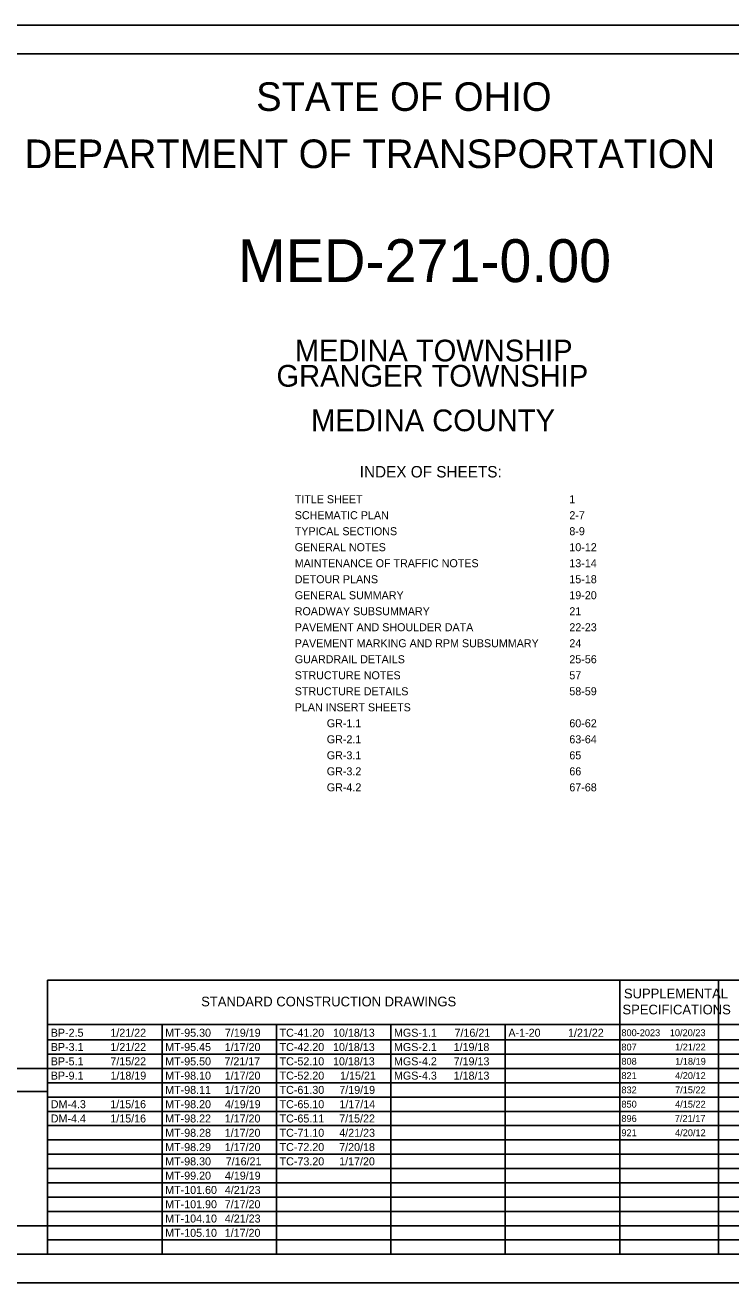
# Model space of a CAD drawing. Extents: x 0 to 34, y 0 to 22.
# Drawn here: x 9.76 to 22.09, y 0 to 22 of the extents above; entities that cross this region are included whole.
import ezdxf

# ---------------------------------------------------------------- set-up
doc = ezdxf.new("R2010")
doc.units = 0
for name, color, linetype in [('SH_Border', 7, 'Continuous'), ('SH_Cut_Line', 7, 'Continuous'), ('SH_Data', 7, 'Continuous'), ('SH_Text', 7, 'Continuous')]:
    doc.layers.add(name, color=color, linetype=linetype)

msp = doc.modelspace()

# ---------------------------------------------------------------- linework, layer by layer
at = {"layer": 'SH_Border'}
msp.add_lwpolyline([(1.5, 21.5), (33.5, 21.5), (33.5, 0.5), (1.5, 0.5)], close=True, dxfattribs=at)
at = {"layer": 'SH_Cut_Line'}
msp.add_lwpolyline([(0, 0), (34, 0), (34, 22), (0, 22)], close=True, dxfattribs=at)
at = {"layer": 'SH_Data'}
for p, q in [((10.15, 5.292), (23.6, 5.292)), ((10.15, 0.5), (10.15, 5.292)), ((20.15, 0.5), (20.15, 5.292)), ((21.875, 0.5), (21.875, 5.292)), ((10.15, 4.521), (23.6, 4.521)), ((12.15, 0.5), (12.15, 4.521)), ((14.15, 0.5), (14.15, 4.521)), ((16.15, 0.5), (16.15, 4.521)), ((18.15, 0.5), (18.15, 4.521)), ((10.15, 4.25), (23.6, 4.25)), ((10.15, 4), (23.6, 4)), ((10.15, 3.75), (7.35, 3.75)), ((10.15, 3.75), (23.6, 3.75)), ((10.15, 0.5), (10.15, 3.75)), ((10.15, 3.35), (7.35, 3.35)), ((10.15, 3.5), (23.6, 3.5)), ((10.15, 3.25), (23.6, 3.25)), ((10.15, 3), (23.6, 3)), ((10.15, 2.75), (23.6, 2.75)), ((10.15, 2.5), (23.6, 2.5)), ((10.15, 2.25), (23.6, 2.25)), ((10.15, 2), (23.6, 2)), ((10.15, 1.75), (23.6, 1.75)), ((10.15, 1.5), (23.6, 1.5)), ((10.15, 1.25), (23.6, 1.25)), ((10.15, 1), (23.6, 1)), ((10.15, 0.75), (23.6, 0.75)), ((10.15, 0.5), (7.35, 0.5))]:
    msp.add_line(p, q, dxfattribs=at)
msp.add_lwpolyline([(10.15, 0.5), (10.15, 1), (7.35, 1), (7.35, 0.5)], close=True, dxfattribs=at)

# ---------------------------------------------------------------- texts
at = {"layer": 'SH_Text'}
for s, height, p in [('STATE OF OHIO', 0.5, (13.795, 20.5)), ('DEPARTMENT OF TRANSPORTATION', 0.5, (9.747, 19.5)), ('MED-271-0.00', 0.75, (13.478, 17.505)), ('MEDINA TOWNSHIP', 0.38, (14.471, 16.118)), ('GRANGER TOWNSHIP', 0.38, (14.151, 15.676)), ('MEDINA COUNTY', 0.38, (14.756, 14.897)), ('INDEX OF SHEETS:', 0.2, (15.606, 14.088)), ('TITLE SHEET', 0.14, (14.47, 13.638)), ('1', 0.14, (19.27, 13.638)), ('SCHEMATIC PLAN', 0.14, (14.47, 13.358)), ('2-7', 0.14, (19.27, 13.358)), ('TYPICAL SECTIONS', 0.14, (14.47, 13.078)), ('8-9', 0.14, (19.27, 13.078)), ('GENERAL NOTES', 0.14, (14.47, 12.798)), ('10-12', 0.14, (19.27, 12.798)), ('MAINTENANCE OF TRAFFIC NOTES', 0.14, (14.47, 12.518)), ('13-14', 0.14, (19.27, 12.518)), ('DETOUR PLANS', 0.14, (14.47, 12.238)), ('15-18', 0.14, (19.27, 12.238)), ('GENERAL SUMMARY', 0.14, (14.47, 11.958)), ('19-20', 0.14, (19.27, 11.958)), ('ROADWAY SUBSUMMARY', 0.14, (14.47, 11.678)), ('21', 0.14, (19.27, 11.678)), ('PAVEMENT AND SHOULDER DATA', 0.14, (14.47, 11.398)), ('22-23', 0.14, (19.27, 11.398)), ('PAVEMENT MARKING AND RPM SUBSUMMARY', 0.14, (14.47, 11.118)), ('24', 0.14, (19.27, 11.118)), ('GUARDRAIL DETAILS', 0.14, (14.47, 10.838)), ('25-56', 0.14, (19.27, 10.838)), ('STRUCTURE NOTES', 0.14, (14.47, 10.558)), ('57', 0.14, (19.27, 10.558)), ('STRUCTURE DETAILS', 0.14, (14.47, 10.278)), ('58-59', 0.14, (19.27, 10.278)), ('PLAN INSERT SHEETS', 0.14, (14.47, 9.998)), ('GR-1.1', 0.14, (15.03, 9.718)), ('60-62', 0.14, (19.27, 9.718)), ('GR-2.1', 0.14, (15.03, 9.438)), ('63-64', 0.14, (19.27, 9.438)), ('GR-3.1', 0.14, (15.03, 9.158)), ('65', 0.14, (19.27, 9.158)), ('GR-3.2', 0.14, (15.03, 8.878)), ('66', 0.14, (19.27, 8.878)), ('GR-4.2', 0.14, (15.03, 8.598)), ('67-68', 0.14, (19.27, 8.598)), ('SUPPLEMENTAL', 0.17, (20.224, 4.976)), ('STANDARD CONSTRUCTION DRAWINGS', 0.17, (12.834, 4.836)), ('SPECIFICATIONS', 0.17, (20.198, 4.696)), ('BP-2.5', 0.14, (10.205, 4.305)), ('1/21/22', 0.14, (11.247, 4.305)), ('MT-95.30', 0.14, (12.205, 4.305)), ('7/19/19', 0.14, (13.249, 4.305)), ('TC-41.20', 0.14, (14.205, 4.305)), ('10/18/13', 0.14, (15.139, 4.305)), ('MGS-1.1', 0.14, (16.205, 4.305)), ('7/16/21', 0.14, (17.263, 4.305)), ('A-1-20', 0.14, (18.205, 4.305)), ('1/21/22', 0.14, (19.247, 4.305)), ('800-2023', 0.12, (20.18, 4.315)), ('10/20/23', 0.12, (21.026, 4.315)), ('BP-3.1', 0.14, (10.205, 4.055)), ('1/21/22', 0.14, (11.247, 4.055)), ('MT-95.45', 0.14, (12.205, 4.055)), ('1/17/20', 0.14, (13.246, 4.055)), ('TC-42.20', 0.14, (14.205, 4.055)), ('10/18/13', 0.14, (15.139, 4.055)), ('MGS-2.1', 0.14, (16.205, 4.055)), ('1/19/18', 0.14, (17.247, 4.055)), ('807', 0.12, (20.18, 4.065)), ('1/21/22', 0.12, (21.118, 4.065)), ('BP-5.1', 0.14, (10.205, 3.805)), ('7/15/22', 0.14, (11.247, 3.805)), ('MT-95.50', 0.14, (12.205, 3.805)), ('7/21/17', 0.14, (13.241, 3.805)), ('TC-52.10', 0.14, (14.205, 3.805)), ('10/18/13', 0.14, (15.139, 3.805)), ('MGS-4.2', 0.14, (16.205, 3.805)), ('7/19/13', 0.14, (17.248, 3.805)), ('808', 0.12, (20.18, 3.815)), ('1/18/19', 0.12, (21.12, 3.815)), ('BP-9.1', 0.14, (10.205, 3.555)), ('1/18/19', 0.14, (11.249, 3.555)), ('MT-98.10', 0.14, (12.205, 3.555)), ('1/17/20', 0.14, (13.246, 3.555)), ('TC-52.20', 0.14, (14.205, 3.555)), ('1/15/21', 0.14, (15.263, 3.555)), ('MGS-4.3', 0.14, (16.205, 3.555)), ('1/18/13', 0.14, (17.248, 3.555)), ('821', 0.12, (20.18, 3.565)), ('4/20/12', 0.12, (21.118, 3.565)), ('MT-98.11', 0.14, (12.205, 3.305)), ('1/17/20', 0.14, (13.246, 3.305)), ('TC-61.30', 0.14, (14.205, 3.305)), ('7/19/19', 0.14, (15.249, 3.305)), ('832', 0.12, (20.18, 3.315)), ('7/15/22', 0.12, (21.118, 3.315)), ('DM-4.3', 0.14, (10.205, 3.055)), ('1/15/16', 0.14, (11.246, 3.055)), ('MT-98.20', 0.14, (12.205, 3.055)), ('4/19/19', 0.14, (13.249, 3.055)), ('TC-65.10', 0.14, (14.205, 3.055)), ('1/17/14', 0.14, (15.251, 3.055)), ('850', 0.12, (20.18, 3.065)), ('4/15/22', 0.12, (21.118, 3.065)), ('DM-4.4', 0.14, (10.205, 2.805)), ('1/15/16', 0.14, (11.246, 2.805)), ('MT-98.22', 0.14, (12.205, 2.805)), ('1/17/20', 0.14, (13.246, 2.805)), ('TC-65.11', 0.14, (14.205, 2.805)), ('7/15/22', 0.14, (15.247, 2.805)), ('896', 0.12, (20.18, 2.815)), ('7/21/17', 0.12, (21.113, 2.815)), ('MT-98.28', 0.14, (12.205, 2.555)), ('1/17/20', 0.14, (13.246, 2.555)), ('TC-71.10', 0.14, (14.205, 2.555)), ('4/21/23', 0.14, (15.248, 2.555)), ('921', 0.12, (20.18, 2.565)), ('4/20/12', 0.12, (21.118, 2.565)), ('MT-98.29', 0.14, (12.205, 2.305)), ('1/17/20', 0.14, (13.246, 2.305)), ('TC-72.20', 0.14, (14.205, 2.305)), ('7/20/18', 0.14, (15.247, 2.305)), ('7/16/21', 0.14, (13.263, 2.055)), ('1/17/20', 0.14, (15.246, 2.055)), ('MT-98.30', 0.14, (12.205, 2.055)), ('TC-73.20', 0.14, (14.205, 2.055)), ('MT-99.20', 0.14, (12.205, 1.805)), ('4/19/19', 0.14, (13.249, 1.805)), ('MT-101.60', 0.14, (12.205, 1.555)), ('4/21/23', 0.14, (13.248, 1.555)), ('MT-101.90', 0.14, (12.205, 1.305)), ('7/17/20', 0.14, (13.246, 1.305)), ('MT-104.10', 0.14, (12.205, 1.055)), ('4/21/23', 0.14, (13.248, 1.055)), ('MT-105.10', 0.14, (12.205, 0.805)), ('1/17/20', 0.14, (13.246, 0.805))]:
    msp.add_text(s, height=height, dxfattribs=at).set_placement(p)

doc.saveas('drawing.dxf')
